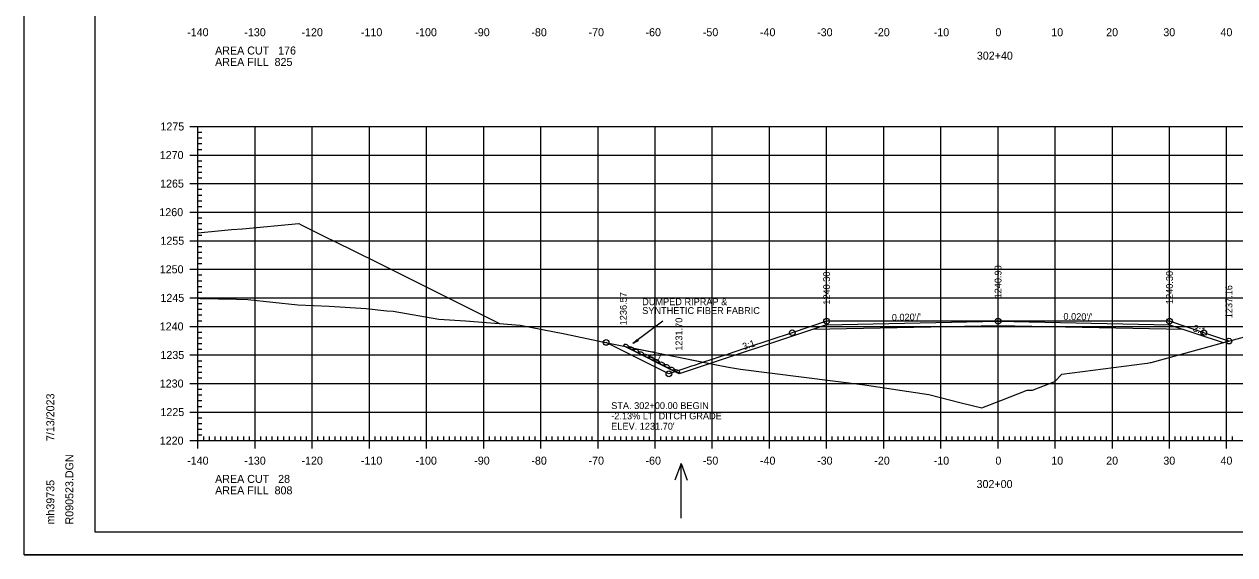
# Model space of a CAD drawing. Extents: x 1406028 to 1412453, y 321733 to 325986.
# Drawn here: x 1410609.2 to 1410821, y 322263.4 to 322356.3 of the extents above; entities that cross this region are included whole.
import ezdxf

# ---------------------------------------------------------------- set-up
doc = ezdxf.new("R2010")
doc.units = 0
for name, color, linetype in [('R_Alt Surface', 7, 'Continuous'), ('R_Axis', 7, 'Continuous'), ('R_Axis Annot', 7, 'Continuous'), ('R_Border', 7, 'Continuous'), ('R_Draft', 7, 'Continuous'), ('R_Drive', 7, 'Continuous'), ('R_Exist Surface', 7, 'Continuous'), ('R_Fin Surface', 7, 'Continuous'), ('R_Fin Surface Annot', 7, 'Continuous'), ('R_Grid', 7, 'Continuous'), ('R_No Plot', 7, 'Continuous'), ('R_Water Annot', 7, 'Continuous')]:
    doc.layers.add(name, color=color, linetype=linetype)

msp = doc.modelspace()

# ---------------------------------------------------------------- linework, layer by layer
at = {"layer": 'R_Alt Surface'}
msp.add_lwpolyline([(1410747.2, 322302.93), (1410779.59, 322303.58), (1410811.99, 322302.93)], dxfattribs=at)
at = {"layer": 'R_Axis'}
for p, q in [((1410638.19, 322338.43), (1410640.99, 322338.43)), ((1410639.59, 322283.43), (1410639.59, 322338.43)), ((1410639.59, 322337.43), (1410640.29, 322337.43)), ((1410639.59, 322336.43), (1410640.29, 322336.43)), ((1410639.59, 322335.43), (1410640.29, 322335.43)), ((1410638.19, 322333.43), (1410640.99, 322333.43)), ((1410639.59, 322334.43), (1410640.29, 322334.43)), ((1410639.59, 322332.43), (1410640.29, 322332.43)), ((1410639.59, 322331.43), (1410640.29, 322331.43)), ((1410639.59, 322330.43), (1410640.29, 322330.43)), ((1410639.59, 322329.43), (1410640.29, 322329.43)), ((1410638.19, 322328.43), (1410640.99, 322328.43)), ((1410639.59, 322327.43), (1410640.29, 322327.43)), ((1410639.59, 322326.43), (1410640.29, 322326.43)), ((1410639.59, 322325.43), (1410640.29, 322325.43)), ((1410638.19, 322323.43), (1410640.99, 322323.43)), ((1410639.59, 322324.43), (1410640.29, 322324.43)), ((1410639.59, 322322.43), (1410640.29, 322322.43)), ((1410639.59, 322321.43), (1410640.29, 322321.43)), ((1410638.19, 322318.43), (1410640.99, 322318.43)), ((1410639.59, 322320.43), (1410640.29, 322320.43)), ((1410639.59, 322319.43), (1410640.29, 322319.43)), ((1410639.59, 322317.43), (1410640.29, 322317.43)), ((1410639.59, 322316.43), (1410640.29, 322316.43)), ((1410639.59, 322315.43), (1410640.29, 322315.43)), ((1410639.59, 322314.43), (1410640.29, 322314.43)), ((1410638.19, 322313.43), (1410640.99, 322313.43)), ((1410639.59, 322312.43), (1410640.29, 322312.43)), ((1410639.59, 322311.43), (1410640.29, 322311.43)), ((1410639.59, 322310.43), (1410640.29, 322310.43)), ((1410638.19, 322308.43), (1410640.99, 322308.43)), ((1410639.59, 322309.43), (1410640.29, 322309.43)), ((1410639.59, 322307.43), (1410640.29, 322307.43)), ((1410639.59, 322306.43), (1410640.29, 322306.43)), ((1410639.59, 322305.43), (1410640.29, 322305.43)), ((1410639.59, 322304.43), (1410640.29, 322304.43)), ((1410638.19, 322303.43), (1410640.99, 322303.43)), ((1410639.59, 322302.43), (1410640.29, 322302.43)), ((1410639.59, 322301.43), (1410640.29, 322301.43)), ((1410639.59, 322300.43), (1410640.29, 322300.43)), ((1410639.59, 322299.43), (1410640.29, 322299.43)), ((1410638.19, 322298.43), (1410640.99, 322298.43)), ((1410639.59, 322297.43), (1410640.29, 322297.43)), ((1410639.59, 322296.43), (1410640.29, 322296.43)), ((1410639.59, 322295.43), (1410640.29, 322295.43)), ((1410638.19, 322293.43), (1410640.99, 322293.43)), ((1410639.59, 322294.43), (1410640.29, 322294.43)), ((1410639.59, 322292.43), (1410640.29, 322292.43)), ((1410639.59, 322291.43), (1410640.29, 322291.43)), ((1410639.59, 322290.43), (1410640.29, 322290.43)), ((1410639.59, 322289.43), (1410640.29, 322289.43)), ((1410638.19, 322288.43), (1410640.99, 322288.43)), ((1410639.59, 322287.43), (1410640.29, 322287.43)), ((1410639.59, 322286.43), (1410640.29, 322286.43)), ((1410639.59, 322285.43), (1410640.29, 322285.43)), ((1410639.59, 322282.03), (1410639.59, 322284.83)), ((1410649.59, 322282.03), (1410649.59, 322284.83)), ((1410659.59, 322282.03), (1410659.59, 322284.83)), ((1410669.59, 322282.03), (1410669.59, 322284.83)), ((1410679.59, 322282.03), (1410679.59, 322284.83)), ((1410689.59, 322282.03), (1410689.59, 322284.83)), ((1410699.59, 322282.03), (1410699.59, 322284.83)), ((1410709.59, 322282.03), (1410709.59, 322284.83)), ((1410719.59, 322282.03), (1410719.59, 322284.83)), ((1410729.59, 322282.03), (1410729.59, 322284.83)), ((1410739.59, 322282.03), (1410739.59, 322284.83)), ((1410749.59, 322282.03), (1410749.59, 322284.83)), ((1410759.59, 322282.03), (1410759.59, 322284.83)), ((1410769.59, 322282.03), (1410769.59, 322284.83)), ((1410779.59, 322282.03), (1410779.59, 322284.83)), ((1410789.59, 322282.03), (1410789.59, 322284.83)), ((1410799.59, 322282.03), (1410799.59, 322284.83)), ((1410809.59, 322282.03), (1410809.59, 322284.83)), ((1410819.59, 322282.03), (1410819.59, 322284.83)), ((1410638.19, 322283.43), (1410640.99, 322283.43)), ((1410639.59, 322284.43), (1410640.29, 322284.43)), ((1410639.59, 322283.43), (1410919.59, 322283.43)), ((1410640.59, 322283.43), (1410640.59, 322284.13)), ((1410641.59, 322283.43), (1410641.59, 322284.13)), ((1410642.59, 322283.43), (1410642.59, 322284.13)), ((1410643.59, 322283.43), (1410643.59, 322284.13)), ((1410644.59, 322283.43), (1410644.59, 322284.13)), ((1410645.59, 322283.43), (1410645.59, 322284.13)), ((1410646.59, 322283.43), (1410646.59, 322284.13)), ((1410647.59, 322283.43), (1410647.59, 322284.13)), ((1410648.59, 322283.43), (1410648.59, 322284.13)), ((1410650.59, 322283.43), (1410650.59, 322284.13)), ((1410651.59, 322283.43), (1410651.59, 322284.13)), ((1410652.59, 322283.43), (1410652.59, 322284.13)), ((1410653.59, 322283.43), (1410653.59, 322284.13)), ((1410654.59, 322283.43), (1410654.59, 322284.13)), ((1410655.59, 322283.43), (1410655.59, 322284.13)), ((1410656.59, 322283.43), (1410656.59, 322284.13)), ((1410657.59, 322283.43), (1410657.59, 322284.13)), ((1410658.59, 322283.43), (1410658.59, 322284.13)), ((1410660.59, 322283.43), (1410660.59, 322284.13)), ((1410661.59, 322283.43), (1410661.59, 322284.13)), ((1410662.59, 322283.43), (1410662.59, 322284.13)), ((1410663.59, 322283.43), (1410663.59, 322284.13)), ((1410664.59, 322283.43), (1410664.59, 322284.13)), ((1410665.59, 322283.43), (1410665.59, 322284.13)), ((1410666.59, 322283.43), (1410666.59, 322284.13)), ((1410667.59, 322283.43), (1410667.59, 322284.13)), ((1410668.59, 322283.43), (1410668.59, 322284.13)), ((1410670.59, 322283.43), (1410670.59, 322284.13)), ((1410671.59, 322283.43), (1410671.59, 322284.13)), ((1410672.59, 322283.43), (1410672.59, 322284.13)), ((1410673.59, 322283.43), (1410673.59, 322284.13)), ((1410674.59, 322283.43), (1410674.59, 322284.13)), ((1410675.59, 322283.43), (1410675.59, 322284.13)), ((1410676.59, 322283.43), (1410676.59, 322284.13)), ((1410677.59, 322283.43), (1410677.59, 322284.13)), ((1410678.59, 322283.43), (1410678.59, 322284.13)), ((1410680.59, 322283.43), (1410680.59, 322284.13)), ((1410681.59, 322283.43), (1410681.59, 322284.13)), ((1410682.59, 322283.43), (1410682.59, 322284.13)), ((1410683.59, 322283.43), (1410683.59, 322284.13)), ((1410684.59, 322283.43), (1410684.59, 322284.13)), ((1410685.59, 322283.43), (1410685.59, 322284.13)), ((1410686.59, 322283.43), (1410686.59, 322284.13)), ((1410687.59, 322283.43), (1410687.59, 322284.13)), ((1410688.59, 322283.43), (1410688.59, 322284.13)), ((1410690.59, 322283.43), (1410690.59, 322284.13)), ((1410691.59, 322283.43), (1410691.59, 322284.13)), ((1410692.59, 322283.43), (1410692.59, 322284.13)), ((1410693.59, 322283.43), (1410693.59, 322284.13)), ((1410694.59, 322283.43), (1410694.59, 322284.13)), ((1410695.59, 322283.43), (1410695.59, 322284.13)), ((1410696.59, 322283.43), (1410696.59, 322284.13)), ((1410697.59, 322283.43), (1410697.59, 322284.13)), ((1410698.59, 322283.43), (1410698.59, 322284.13)), ((1410700.59, 322283.43), (1410700.59, 322284.13)), ((1410701.59, 322283.43), (1410701.59, 322284.13)), ((1410702.59, 322283.43), (1410702.59, 322284.13)), ((1410703.59, 322283.43), (1410703.59, 322284.13)), ((1410704.59, 322283.43), (1410704.59, 322284.13)), ((1410705.59, 322283.43), (1410705.59, 322284.13)), ((1410706.59, 322283.43), (1410706.59, 322284.13)), ((1410707.59, 322283.43), (1410707.59, 322284.13)), ((1410708.59, 322283.43), (1410708.59, 322284.13)), ((1410710.59, 322283.43), (1410710.59, 322284.13)), ((1410711.59, 322283.43), (1410711.59, 322284.13)), ((1410712.59, 322283.43), (1410712.59, 322284.13)), ((1410713.59, 322283.43), (1410713.59, 322284.13)), ((1410714.59, 322283.43), (1410714.59, 322284.13)), ((1410715.59, 322283.43), (1410715.59, 322284.13)), ((1410716.59, 322283.43), (1410716.59, 322284.13)), ((1410717.59, 322283.43), (1410717.59, 322284.13)), ((1410718.59, 322283.43), (1410718.59, 322284.13)), ((1410720.59, 322283.43), (1410720.59, 322284.13)), ((1410721.59, 322283.43), (1410721.59, 322284.13)), ((1410722.59, 322283.43), (1410722.59, 322284.13)), ((1410723.59, 322283.43), (1410723.59, 322284.13)), ((1410724.59, 322283.43), (1410724.59, 322284.13)), ((1410725.59, 322283.43), (1410725.59, 322284.13)), ((1410726.59, 322283.43), (1410726.59, 322284.13)), ((1410727.59, 322283.43), (1410727.59, 322284.13)), ((1410728.59, 322283.43), (1410728.59, 322284.13)), ((1410730.59, 322283.43), (1410730.59, 322284.13)), ((1410731.59, 322283.43), (1410731.59, 322284.13)), ((1410732.59, 322283.43), (1410732.59, 322284.13)), ((1410733.59, 322283.43), (1410733.59, 322284.13)), ((1410734.59, 322283.43), (1410734.59, 322284.13)), ((1410735.59, 322283.43), (1410735.59, 322284.13)), ((1410736.59, 322283.43), (1410736.59, 322284.13)), ((1410737.59, 322283.43), (1410737.59, 322284.13)), ((1410738.59, 322283.43), (1410738.59, 322284.13)), ((1410740.59, 322283.43), (1410740.59, 322284.13)), ((1410741.59, 322283.43), (1410741.59, 322284.13)), ((1410742.59, 322283.43), (1410742.59, 322284.13)), ((1410743.59, 322283.43), (1410743.59, 322284.13)), ((1410744.59, 322283.43), (1410744.59, 322284.13)), ((1410745.59, 322283.43), (1410745.59, 322284.13)), ((1410746.59, 322283.43), (1410746.59, 322284.13)), ((1410747.59, 322283.43), (1410747.59, 322284.13)), ((1410748.59, 322283.43), (1410748.59, 322284.13)), ((1410750.59, 322283.43), (1410750.59, 322284.13)), ((1410751.59, 322283.43), (1410751.59, 322284.13)), ((1410752.59, 322283.43), (1410752.59, 322284.13)), ((1410753.59, 322283.43), (1410753.59, 322284.13)), ((1410754.59, 322283.43), (1410754.59, 322284.13)), ((1410755.59, 322283.43), (1410755.59, 322284.13)), ((1410756.59, 322283.43), (1410756.59, 322284.13)), ((1410757.59, 322283.43), (1410757.59, 322284.13)), ((1410758.59, 322283.43), (1410758.59, 322284.13)), ((1410760.59, 322283.43), (1410760.59, 322284.13)), ((1410761.59, 322283.43), (1410761.59, 322284.13)), ((1410762.59, 322283.43), (1410762.59, 322284.13)), ((1410763.59, 322283.43), (1410763.59, 322284.13)), ((1410764.59, 322283.43), (1410764.59, 322284.13)), ((1410765.59, 322283.43), (1410765.59, 322284.13)), ((1410766.59, 322283.43), (1410766.59, 322284.13)), ((1410767.59, 322283.43), (1410767.59, 322284.13)), ((1410768.59, 322283.43), (1410768.59, 322284.13)), ((1410770.59, 322283.43), (1410770.59, 322284.13)), ((1410771.59, 322283.43), (1410771.59, 322284.13)), ((1410772.59, 322283.43), (1410772.59, 322284.13)), ((1410773.59, 322283.43), (1410773.59, 322284.13)), ((1410774.59, 322283.43), (1410774.59, 322284.13)), ((1410775.59, 322283.43), (1410775.59, 322284.13)), ((1410776.59, 322283.43), (1410776.59, 322284.13)), ((1410777.59, 322283.43), (1410777.59, 322284.13)), ((1410778.59, 322283.43), (1410778.59, 322284.13)), ((1410780.59, 322283.43), (1410780.59, 322284.13)), ((1410781.59, 322283.43), (1410781.59, 322284.13)), ((1410782.59, 322283.43), (1410782.59, 322284.13)), ((1410783.59, 322283.43), (1410783.59, 322284.13)), ((1410784.59, 322283.43), (1410784.59, 322284.13)), ((1410785.59, 322283.43), (1410785.59, 322284.13)), ((1410786.59, 322283.43), (1410786.59, 322284.13)), ((1410787.59, 322283.43), (1410787.59, 322284.13)), ((1410788.59, 322283.43), (1410788.59, 322284.13)), ((1410790.59, 322283.43), (1410790.59, 322284.13)), ((1410791.59, 322283.43), (1410791.59, 322284.13)), ((1410792.59, 322283.43), (1410792.59, 322284.13)), ((1410793.59, 322283.43), (1410793.59, 322284.13)), ((1410794.59, 322283.43), (1410794.59, 322284.13)), ((1410795.59, 322283.43), (1410795.59, 322284.13)), ((1410796.59, 322283.43), (1410796.59, 322284.13)), ((1410797.59, 322283.43), (1410797.59, 322284.13)), ((1410798.59, 322283.43), (1410798.59, 322284.13)), ((1410800.59, 322283.43), (1410800.59, 322284.13)), ((1410801.59, 322283.43), (1410801.59, 322284.13)), ((1410802.59, 322283.43), (1410802.59, 322284.13)), ((1410803.59, 322283.43), (1410803.59, 322284.13)), ((1410804.59, 322283.43), (1410804.59, 322284.13)), ((1410805.59, 322283.43), (1410805.59, 322284.13)), ((1410806.59, 322283.43), (1410806.59, 322284.13)), ((1410807.59, 322283.43), (1410807.59, 322284.13)), ((1410808.59, 322283.43), (1410808.59, 322284.13)), ((1410810.59, 322283.43), (1410810.59, 322284.13)), ((1410811.59, 322283.43), (1410811.59, 322284.13)), ((1410812.59, 322283.43), (1410812.59, 322284.13)), ((1410813.59, 322283.43), (1410813.59, 322284.13)), ((1410814.59, 322283.43), (1410814.59, 322284.13)), ((1410815.59, 322283.43), (1410815.59, 322284.13)), ((1410816.59, 322283.43), (1410816.59, 322284.13)), ((1410817.59, 322283.43), (1410817.59, 322284.13)), ((1410818.59, 322283.43), (1410818.59, 322284.13)), ((1410820.59, 322283.43), (1410820.59, 322284.13))]:
    msp.add_line(p, q, dxfattribs=at)
at = {"layer": 'R_Border'}
for p, q in [((1410621.59, 322267.43), (1410621.59, 322472.89)), ((1410621.59, 322267.43), (1410621.59, 322267.43)), ((1410937.77, 322267.43), (1410621.59, 322267.43))]:
    msp.add_line(p, q, dxfattribs=at)
at = {"layer": 'R_Draft'}
for p, q in [((1410720.94, 322304.33), (1410715.71, 322300.41)), ((1410716.42, 322301.13), (1410715.71, 322300.41)), ((1410716.6, 322300.89), (1410715.71, 322300.41)), ((1410716.43, 322301.11), (1410715.84, 322300.51)), ((1410716.58, 322300.91), (1410715.84, 322300.51)), ((1410716.45, 322301.09), (1410715.98, 322300.61)), ((1410716.57, 322300.93), (1410715.98, 322300.61)), ((1410716.46, 322301.07), (1410716.11, 322300.71)), ((1410716.55, 322300.95), (1410716.11, 322300.71)), ((1410716.48, 322301.05), (1410716.25, 322300.81)), ((1410716.54, 322300.97), (1410716.25, 322300.81)), ((1410716.49, 322301.03), (1410716.38, 322300.91)), ((1410716.52, 322300.99), (1410716.38, 322300.91)), ((1410716.42, 322301.13), (1410716.6, 322300.89))]:
    msp.add_line(p, q, dxfattribs=at)
for centre in [(1410714.53, 322300.05), (1410715.42, 322299.61), (1410716.32, 322299.16), (1410717.21, 322298.71), (1410718.11, 322298.27), (1410719, 322297.82), (1410719.9, 322297.37), (1410720.79, 322296.92), (1410721.68, 322296.48), (1410722.58, 322296.03), (1410723.47, 322295.58)]:
    msp.add_ellipse(centre, major_axis=(0.389, -0.201), ratio=0.517889, dxfattribs=at)
at = {"layer": 'R_Exist Surface'}
msp.add_lwpolyline([(1410639.59, 322308.35), (1410639.99, 322308.32), (1410646.33, 322308.21), (1410648.3, 322308.14), (1410657.07, 322307.18), (1410662.55, 322306.97), (1410669.01, 322306.55), (1410672.61, 322306.13), (1410673.75, 322306.11), (1410681.71, 322304.7), (1410686.4, 322304.41), (1410695.97, 322303.64), (1410703.8, 322302.15), (1410711.46, 322300.52), (1410730.3, 322296.7), (1410732.42, 322296.31), (1410734.54, 322295.94), (1410756.25, 322293.21), (1410767.48, 322291.52), (1410773.14, 322290.06), (1410776.76, 322289.17), (1410780.07, 322290.45), (1410784.66, 322292.27), (1410785.62, 322292.24), (1410789.54, 322293.8), (1410790.75, 322295.07), (1410805.23, 322296.93), (1410805.74, 322296.98), (1410806.23, 322297.1), (1410806.41, 322297.12), (1410818.88, 322300.56), (1410871.35, 322314.92)], dxfattribs=at)
at = {"layer": 'R_Fin Surface'}
for p, q in [((1410749.59, 322303.73), (1410723.79, 322295.13)), ((1410809.59, 322303.73), (1410819, 322300.59)), ((1410723.79, 322295.13), (1410714.05, 322300))]:
    msp.add_line(p, q, dxfattribs=at)
for points in [[(1410639.59, 322319.83), (1410643.1, 322320.15), (1410645.48, 322320.37), (1410647.36, 322320.54), (1410657.22, 322321.45), (1410657.22, 322321.45), (1410657.24, 322321.45), (1410657.67, 322321.23), (1410661.99, 322319.07), (1410663.42, 322318.36), (1410670.86, 322314.65), (1410688.36, 322305.91), (1410692.33, 322303.93)], [(1410749.59, 322303.73), (1410779.59, 322304.33), (1410809.59, 322303.73)]]:
    msp.add_lwpolyline(points, dxfattribs=at)
at = {"layer": 'R_Grid'}
for p, q in [((1410639.59, 322338.43), (1410919.59, 322338.43)), ((1410639.59, 322283.43), (1410639.59, 322338.43)), ((1410649.59, 322283.43), (1410649.59, 322338.43)), ((1410659.59, 322283.43), (1410659.59, 322338.43)), ((1410669.59, 322283.43), (1410669.59, 322338.43)), ((1410679.59, 322283.43), (1410679.59, 322338.43)), ((1410689.59, 322283.43), (1410689.59, 322338.43)), ((1410699.59, 322283.43), (1410699.59, 322338.43)), ((1410709.59, 322283.43), (1410709.59, 322338.43)), ((1410719.59, 322283.43), (1410719.59, 322338.43)), ((1410729.59, 322283.43), (1410729.59, 322338.43)), ((1410739.59, 322283.43), (1410739.59, 322338.43)), ((1410749.59, 322283.43), (1410749.59, 322338.43)), ((1410759.59, 322283.43), (1410759.59, 322338.43)), ((1410769.59, 322283.43), (1410769.59, 322338.43)), ((1410779.59, 322283.43), (1410779.59, 322338.43)), ((1410789.59, 322283.43), (1410789.59, 322338.43)), ((1410799.59, 322283.43), (1410799.59, 322338.43)), ((1410809.59, 322283.43), (1410809.59, 322338.43)), ((1410819.59, 322283.43), (1410819.59, 322338.43)), ((1410639.59, 322333.43), (1410919.59, 322333.43)), ((1410639.59, 322328.43), (1410919.59, 322328.43)), ((1410639.59, 322323.43), (1410919.59, 322323.43)), ((1410639.59, 322318.43), (1410919.59, 322318.43)), ((1410639.59, 322313.43), (1410919.59, 322313.43)), ((1410639.59, 322308.43), (1410919.59, 322308.43)), ((1410639.59, 322303.43), (1410919.59, 322303.43)), ((1410639.59, 322298.43), (1410919.59, 322298.43)), ((1410639.59, 322293.43), (1410919.59, 322293.43)), ((1410639.59, 322288.43), (1410919.59, 322288.43)), ((1410639.59, 322283.43), (1410919.59, 322283.43))]:
    msp.add_line(p, q, dxfattribs=at)
at = {"layer": 'R_No Plot'}
msp.add_line((1410609.19, 322263.45), (1410942.52, 322263.45), dxfattribs=at)
for points in [[(1410609.18, 322476.78), (1410942.52, 322476.78), (1410942.52, 322263.44), (1410609.18, 322263.44)], [(1410855.51, 322472.89), (1410875.13, 322472.89), (1410875.13, 322463.01), (1410891.24, 322463.01), (1410914.44, 322463.01), (1410914.44, 322438.67), (1410937.77, 322438.67), (1410937.77, 322267.43), (1410621.59, 322267.43), (1410621.59, 322472.89)], [(1410728.06, 322297.15), (1410730.3, 322296.7), (1410732.42, 322296.31), (1410734.54, 322295.94), (1410756.25, 322293.21), (1410767.48, 322291.52), (1410773.14, 322290.06), (1410776.76, 322289.17), (1410780.07, 322290.45), (1410784.66, 322292.27), (1410785.62, 322292.24), (1410789.54, 322293.8), (1410790.75, 322295.07), (1410805.23, 322296.93), (1410805.74, 322296.98), (1410806.23, 322297.1), (1410806.41, 322297.12), (1410818.88, 322300.56), (1410819.99, 322300.86), (1410815.59, 322302.33), (1410809.59, 322304.33), (1410779.59, 322304.33), (1410749.59, 322304.33), (1410743.59, 322302.33), (1410735.77, 322299.72), (1410733.17, 322298.85), (1410731.87, 322298.42), (1410731.08, 322298.16), (1410730.56, 322297.98), (1410730.19, 322297.86), (1410729.91, 322297.77), (1410729.69, 322297.7), (1410729.52, 322297.64)], [(1410711.01, 322300.62), (1410711.46, 322300.52), (1410728.06, 322297.15), (1410727.33, 322296.91), (1410727.26, 322296.89), (1410727.18, 322296.86), (1410727.08, 322296.82), (1410726.94, 322296.78), (1410726.74, 322296.71), (1410726.44, 322296.61), (1410725.95, 322296.45), (1410724.96, 322296.12), (1410721.99, 322295.13)]]:
    msp.add_lwpolyline(points, close=True, dxfattribs=at)
for centre in [(1410749.59, 322304.33), (1410749.59, 322304.33), (1410779.59, 322304.33), (1410809.59, 322304.33), (1410809.59, 322304.33), (1410743.59, 322302.33), (1410815.59, 322302.33), (1410711.01, 322300.62), (1410819.99, 322300.86), (1410721.99, 322295.13), (1410721.99, 322295.13)]:
    msp.add_circle(centre, 0.5, dxfattribs=at)
at = {"layer": 'R_Water Annot'}
for p, q in [((1410724.13, 322279.43), (1410723.06, 322276.5)), ((1410724.13, 322269.86), (1410724.13, 322279.43)), ((1410724.13, 322279.43), (1410725.2, 322276.5))]:
    msp.add_line(p, q, dxfattribs=at)

# ---------------------------------------------------------------- texts
at = {"layer": 'R_Axis Annot'}
for s, p in [('-140', (1410637.7, 322354.23)), ('-130', (1410647.7, 322354.23)), ('-120', (1410657.7, 322354.23)), ('-110', (1410668.1, 322354.23)), ('-100', (1410677.65, 322354.23)), ('-90', (1410687.93, 322354.23)), ('-80', (1410697.93, 322354.23)), ('-70', (1410707.93, 322354.23)), ('-60', (1410717.9, 322354.23)), ('-50', (1410727.93, 322354.23)), ('-40', (1410737.93, 322354.23)), ('-30', (1410747.93, 322354.23)), ('-20', (1410757.93, 322354.23)), ('-10', (1410768.33, 322354.23)), ('0', (1410779.13, 322354.23)), ('10', (1410788.9, 322354.23)), ('20', (1410798.51, 322354.23)), ('30', (1410808.51, 322354.23)), ('40', (1410818.51, 322354.23)), ('AREA CUT   176', (1410642.59, 322351.03)), ('AREA FILL  825', (1410642.59, 322349.03)), ('302+40', (1410775.88, 322350.13)), ('1275', (1410633.02, 322337.73)), ('1270', (1410632.9, 322332.73)), ('1265', (1410632.96, 322327.73)), ('1260', (1410632.83, 322322.73)), ('1255', (1410633.02, 322317.73)), ('1250', (1410632.9, 322312.73)), ('1245', (1410633.02, 322307.73)), ('1240', (1410632.9, 322302.73)), ('1235', (1410633.02, 322297.73)), ('1230', (1410632.9, 322292.73)), ('1225', (1410633.02, 322287.73)), ('1220', (1410632.9, 322282.73)), ('-140', (1410637.7, 322279.23)), ('-130', (1410647.7, 322279.23)), ('-120', (1410657.7, 322279.23)), ('-110', (1410668.1, 322279.23)), ('-100', (1410677.65, 322279.23)), ('-90', (1410687.93, 322279.23)), ('-80', (1410697.93, 322279.23)), ('-70', (1410707.93, 322279.23)), ('-60', (1410717.9, 322279.23)), ('-50', (1410727.93, 322279.23)), ('-40', (1410737.93, 322279.23)), ('-30', (1410747.93, 322279.23)), ('-20', (1410757.93, 322279.23)), ('-10', (1410768.33, 322279.23)), ('0', (1410779.13, 322279.23)), ('10', (1410788.9, 322279.23)), ('20', (1410798.51, 322279.23)), ('30', (1410808.51, 322279.23)), ('40', (1410818.51, 322279.23)), ('AREA CUT   28', (1410642.59, 322276.03)), ('302+00', (1410775.83, 322275.13)), ('AREA FILL  808', (1410642.59, 322274.03))]:
    msp.add_text(s, height=1.4, dxfattribs=at).set_placement(p)
at = {"layer": 'R_Border'}
for s, p in [('7/13/2023', (1410614.46, 322283.35)), ('R090523.DGN', (1410617.78, 322268.75)), ('mh39735', (1410614.46, 322268.75))]:
    msp.add_text(s, height=1.4, rotation=90, dxfattribs=at).set_placement(p)
at = {"layer": 'R_Draft'}
for s, p in [('DUMPED RIPRAP &', (1410717.32, 322307.14)), ('SYNTHETIC FIBER FABRIC', (1410717.32, 322305.6))]:
    msp.add_text(s, height=1.2, dxfattribs=at).set_placement(p)
at = {"layer": 'R_Drive'}
for s, p in [('STA. 302+00.00 BEGIN', (1410711.9, 322288.96)), ('-2.13% LT. DITCH GRADE', (1410711.9, 322287.16)), ("ELEV. 1231.70'", (1410711.9, 322285.36))]:
    msp.add_text(s, height=1.2, dxfattribs=at).set_placement(p)
at = {"layer": 'R_Fin Surface Annot'}
for s, rotation, p in [('1240.30', 90, (1410750.19, 322307.23)), ('1240.90', 90, (1410780.19, 322308.33)), ('1240.30', 90, (1410810.19, 322307.34)), ('1237.16', 90, (1410820.59, 322304.86)), ('1236.57', 90, (1410714.62, 322303.62)), ("0.020'/'", 1.1458, (1410761.01, 322304.4)), ("0.020'/'", 358.8542, (1410791.02, 322304.59)), ('1231.70', 90, (1410724.35, 322299.16)), ('3:1', 341.5651, (1410813.58, 322302.64)), ('3:1', 18.4349, (1410735.09, 322299.28)), ('2:1', 333.4349, (1410718.4, 322298.14))]:
    msp.add_text(s, height=1.2, rotation=rotation, dxfattribs=at).set_placement(p)

doc.saveas('drawing.dxf')
